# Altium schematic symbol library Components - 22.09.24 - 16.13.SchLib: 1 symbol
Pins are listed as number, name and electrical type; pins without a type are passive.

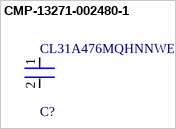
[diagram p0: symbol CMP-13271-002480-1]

## CMP-13271-002480-1
designator C?, comment CL31A476MQHNNWE
Cap Ceramic 47uF 6.3V X5R ±20% SMD 1206 +85°C Embossed T/R
footprint FP-CL31-IPC_C
footprint FP-CL31-IPC_A
footprint FP-CL31-IPC_B
pins: 1, 2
